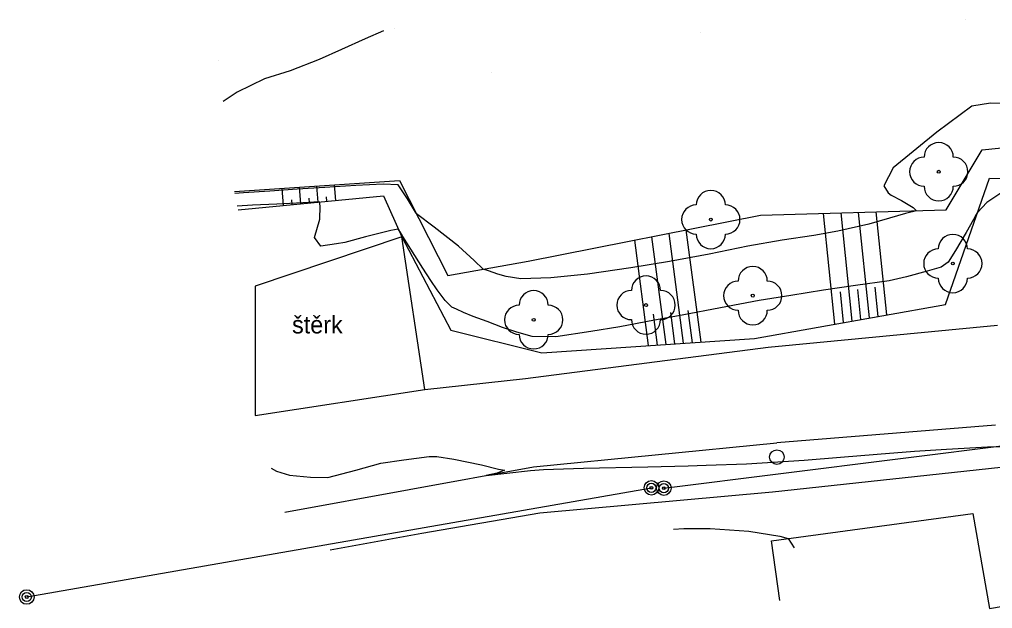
# Model space of a CAD drawing. Extents: x -448957 to -448612, y -1107690 to -1107245.
# Drawn here: x -448905.6 to -448872.22, y -1107404.31 to -1107384.1 of the extents above; entities that cross this region are included whole.
import ezdxf

# ---------------------------------------------------------------- set-up
doc = ezdxf.new("R2010")
doc.units = 0
for name, color, linetype in [('22', 7, 'Continuous'), ('25', 7, 'Continuous'), ('28', 7, 'Continuous'), ('Default', 7, 'Continuous'), ('Vrstva 1', 7, 'Continuous'), ('Vrstva 10', 7, 'Continuous'), ('Vrstva 11', 7, 'Continuous'), ('Vrstva 14', 7, 'Continuous'), ('Vrstva 15', 7, 'Continuous'), ('Vrstva 16', 7, 'Continuous'), ('Vrstva 17', 7, 'Continuous'), ('Vrstva 22', 7, 'Continuous'), ('Vrstva 25', 7, 'Continuous'), ('Vrstva 28', 7, 'Continuous'), ('Vrstva 40', 7, 'Continuous'), ('Vrstva 5', 7, 'Continuous'), ('Vrstva 53', 7, 'Continuous'), ('Vrstva 7', 7, 'Continuous'), ('Vrstva 8', 7, 'Continuous')]:
    doc.layers.add(name, color=color, linetype=linetype)

# ---------------------------------------------------------------- blocks, each defined once
blk = doc.blocks.new('POINT_DISPLAY')
at = {"layer": 'Default'}
blk.add_line((0, 0), (0, 0), dxfattribs=at)
blk = doc.blocks.new('STROM$5')
at = {"layer": '22'}
blk.add_circle((0, 0), 0.5, dxfattribs=at)
for centre, start, end in [((0, 5), 0, 180), ((-5, 0), 90, 270), ((5, 0), 270, 90), ((0, -5), 180, 0)]:
    blk.add_arc(centre, 5, start, end, dxfattribs=at)
blk = doc.blocks.new('SLB$11')
at = {"layer": '25'}
for radius in [2.5, 1.58, 0.5]:
    blk.add_circle((0, 0), radius, dxfattribs=at)
blk = doc.blocks.new('SV$12')
at = {"layer": '28'}
blk.add_circle((0, 0), 2.5, dxfattribs=at)

msp = doc.modelspace()

# ---------------------------------------------------------------- linework, layer by layer
at = {"layer": 'Vrstva 10'}
for p, q in [((-448879.913, -1107395.339), (-448872.051, -1107394.581)), ((-448888.24, -1107396.414), (-448879.913, -1107395.339)), ((-448891.694, -1107396.794), (-448888.24, -1107396.414)), ((-448897.513, -1107397.681), (-448891.694, -1107396.794)), ((-448872.121, -1107398.014), (-448879.623, -1107398.621)), ((-448887.967, -1107399.449), (-448879.623, -1107398.621)), ((-448896.495, -1107401), (-448887.967, -1107399.449))]:
    msp.add_line(p, q, dxfattribs=at)
at = {"layer": 'Vrstva 11'}
for p, q in [((-448892.481, -1107391.555), (-448897.513, -1107393.245)), ((-448891.694, -1107396.794), (-448892.481, -1107391.555)), ((-448897.513, -1107393.245), (-448897.513, -1107397.681))]:
    msp.add_line(p, q, dxfattribs=at)
at = {"layer": 'Vrstva 14'}
for p, q in [((-448872.575, -1107388.576), (-448868.257, -1107388.103)), ((-448873.805, -1107390.629), (-448872.575, -1107388.576)), ((-448898.226, -1107390.005), (-448892.566, -1107389.622)), ((-448892.566, -1107389.622), (-448890.902, -1107392.878)), ((-448873.839, -1107393.875), (-448872.319, -1107389.541)), ((-448872.319, -1107389.541), (-448868.312, -1107389.677)), ((-448898.1, -1107390.624), (-448893.114, -1107390.15)), ((-448893.114, -1107390.15), (-448892.481, -1107391.555)), ((-448880.177, -1107390.815), (-448873.805, -1107390.629)), ((-448888.143, -1107392.393), (-448880.177, -1107390.815)), ((-448892.481, -1107391.555), (-448890.803, -1107394.756)), ((-448890.902, -1107392.878), (-448888.143, -1107392.393)), ((-448880.382, -1107395.044), (-448873.839, -1107393.875)), ((-448890.803, -1107394.756), (-448887.678, -1107395.533)), ((-448887.678, -1107395.533), (-448880.382, -1107395.044))]:
    msp.add_line(p, q, dxfattribs=at)
at = {"layer": 'Vrstva 15'}
for p, q in [((-448896.541, -1107390.476), (-448896.589, -1107389.894)), ((-448895.944, -1107390.419), (-448895.99, -1107389.854)), ((-448895.347, -1107390.362), (-448895.391, -1107389.813)), ((-448894.749, -1107390.305), (-448894.793, -1107389.773)), ((-448896.243, -1107390.447), (-448896.256, -1107390.286)), ((-448895.645, -1107390.391), (-448895.658, -1107390.234)), ((-448895.048, -1107390.334), (-448895.06, -1107390.182)), ((-448877.625, -1107394.551), (-448878.018, -1107390.752)), ((-448877.033, -1107394.446), (-448877.416, -1107390.734)), ((-448876.441, -1107394.34), (-448876.815, -1107390.717)), ((-448875.848, -1107394.234), (-448876.214, -1107390.699)), ((-448883.415, -1107395.247), (-448883.902, -1107391.553)), ((-448882.815, -1107395.207), (-448883.313, -1107391.436)), ((-448882.215, -1107395.167), (-448882.723, -1107391.319)), ((-448884.015, -1107395.287), (-448884.492, -1107391.67)), ((-448876.144, -1107394.287), (-448876.249, -1107393.277)), ((-448877.329, -1107394.499), (-448877.439, -1107393.438)), ((-448876.737, -1107394.393), (-448876.844, -1107393.358)), ((-448883.715, -1107395.267), (-448883.854, -1107394.212)), ((-448883.115, -1107395.227), (-448883.257, -1107394.15)), ((-448882.515, -1107395.187), (-448882.66, -1107394.088))]:
    msp.add_line(p, q, dxfattribs=at)
at = {"layer": 'Vrstva 16'}
for points in [[(-448871.563, -1107386.992), (-448872.295, -1107386.971), (-448872.932, -1107387.071), (-448874.133, -1107387.971), (-448875.629, -1107389.185), (-448875.946, -1107389.812), (-448875.797, -1107390.049), (-448875.7, -1107390.129), (-448875.337, -1107390.304), (-448874.942, -1107390.546), (-448874.83, -1107390.659), (-448875.201, -1107390.761), (-448875.752, -1107390.917), (-448876.466, -1107391.116), (-448877.53, -1107391.362), (-448878.352, -1107391.509), (-448879.434, -1107391.674), (-448880.611, -1107391.88), (-448881.939, -1107392.149), (-448883.304, -1107392.399), (-448884.63, -1107392.625), (-448886.113, -1107392.835), (-448887.37, -1107392.968), (-448888.402, -1107392.994), (-448888.902, -1107392.918), (-448889.184, -1107392.841), (-448889.508, -1107392.726), (-448889.691, -1107392.665), (-448890.002, -1107392.368), (-448890.54, -1107391.871), (-448891.374, -1107391.22), (-448891.981, -1107390.767), (-448891.996, -1107390.745), (-448892.017, -1107390.71), (-448892.291, -1107390.258), (-448892.61, -1107389.767), (-448893.121, -1107389.745), (-448894.053, -1107389.797), (-448895.126, -1107389.858), (-448896.071, -1107389.923), (-448897.007, -1107389.987), (-448897.906, -1107390.044), (-448898.214, -1107390.065)], [(-448883.16, -1107401.579), (-448882.803, -1107401.562), (-448881.91, -1107401.556), (-448880.584, -1107401.652), (-448879.513, -1107401.822), (-448879.233, -1107401.908), (-448879.02, -1107402.227)]]:
    msp.add_lwpolyline(points, dxfattribs=at)
at = {"layer": 'Vrstva 17'}
for points in [[(-448893.113, -1107384.486), (-448893.737, -1107384.768), (-448894.553, -1107385.127), (-448895.317, -1107385.47), (-448896.316, -1107385.866), (-448897.196, -1107386.132), (-448898.129, -1107386.594), (-448898.611, -1107386.918)], [(-448871.727, -1107389.924), (-448872.418, -1107390.376), (-448872.734, -1107390.723), (-448872.779, -1107390.792), (-448872.874, -1107390.959), (-448873.124, -1107391.408), (-448873.489, -1107392.026), (-448873.739, -1107392.422), (-448873.984, -1107392.596), (-448874.459, -1107392.731), (-448875.171, -1107392.931), (-448875.765, -1107393.07), (-448876.925, -1107393.231), (-448878.014, -1107393.385), (-448879.135, -1107393.565), (-448880.225, -1107393.743), (-448881.546, -1107393.995), (-448882.863, -1107394.243), (-448883.813, -1107394.415), (-448885.007, -1107394.644), (-448885.993, -1107394.804), (-448887.195, -1107394.983), (-448888.014, -1107394.979), (-448888.538, -1107394.825), (-448889.024, -1107394.664), (-448889.556, -1107394.457), (-448890.031, -1107394.287), (-448890.361, -1107394.149), (-448890.602, -1107394.034), (-448890.765, -1107393.967), (-448890.993, -1107393.745), (-448891.264, -1107393.376), (-448891.482, -1107393.057), (-448891.756, -1107392.633), (-448892.177, -1107391.98), (-448892.451, -1107391.545), (-448892.543, -1107391.386), (-448892.601, -1107391.289), (-448892.863, -1107391.34), (-448893.73, -1107391.559), (-448894.439, -1107391.75), (-448894.721, -1107391.8), (-448895.26, -1107391.871), (-448895.473, -1107391.584), (-448895.29, -1107390.949), (-448895.28, -1107390.502), (-448895.305, -1107390.358), (-448895.876, -1107390.388), (-448896.766, -1107390.433), (-448897.604, -1107390.474), (-448898.125, -1107390.5)], [(-448896.957, -1107399.495), (-448896.778, -1107399.591), (-448896.333, -1107399.732), (-448895.615, -1107399.805), (-448895.016, -1107399.812), (-448894.06, -1107399.559), (-448893.204, -1107399.315), (-448892.411, -1107399.204), (-448891.539, -1107399.088), (-448891.278, -1107399.09), (-448890.7, -1107399.179), (-448889.75, -1107399.376), (-448889.166, -1107399.521), (-448888.962, -1107399.56), (-448889.214, -1107399.663), (-448889.592, -1107399.745), (-448888.884, -1107399.659), (-448888.064, -1107399.567), (-448887.618, -1107399.54), (-448886.248, -1107399.495), (-448884.045, -1107399.441), (-448882.664, -1107399.409), (-448882.041, -1107399.39), (-448880.659, -1107399.343), (-448878.686, -1107399.222), (-448877.435, -1107399.112), (-448876.173, -1107399.007), (-448874.894, -1107398.907), (-448873.798, -1107398.843), (-448872.395, -1107398.757), (-448871.785, -1107398.743)]]:
    msp.add_lwpolyline(points, dxfattribs=at)
at = {"layer": 'Vrstva 5'}
for p, q in [((-448879.798, -1107401.985), (-448872.9, -1107401.044)), ((-448872.9, -1107401.044), (-448872.322, -1107404.307)), ((-448879.519, -1107404.032), (-448879.798, -1107401.985)), ((-448872.322, -1107404.307), (-448870.425, -1107403.968))]:
    msp.add_line(p, q, dxfattribs=at)
at = {"layer": 'Vrstva 53'}
for p, q in [((-448883.494, -1107400.177), (-448854.847, -1107396.595)), ((-448905.346, -1107403.911), (-448883.921, -1107400.166))]:
    msp.add_line(p, q, dxfattribs=at)
at = {"layer": 'Vrstva 7'}
for p, q in [((-448879.769, -1107400.301), (-448871.513, -1107399.414)), ((-448887.75, -1107401.024), (-448879.769, -1107400.301)), ((-448891.794, -1107401.725), (-448887.75, -1107401.024))]:
    msp.add_line(p, q, dxfattribs=at)
at = {"layer": 'Vrstva 8'}
msp.add_line((-448894.94, -1107402.29), (-448891.794, -1107401.725), dxfattribs=at)

# ---------------------------------------------------------------- block references
at = {"layer": 'Vrstva 1', "xscale": 0.1, "yscale": 0.10000000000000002}
for p in [(-448872.575, -1107388.576), (-448892.566, -1107389.622), (-448872.319, -1107389.541), (-448898.226, -1107390.005), (-448893.114, -1107390.15), (-448893.114, -1107390.15), (-448898.1, -1107390.624), (-448873.805, -1107390.629), (-448880.177, -1107390.815), (-448892.481, -1107391.555), (-448892.481, -1107391.555), (-448892.481, -1107391.555), (-448888.143, -1107392.393), (-448890.902, -1107392.878), (-448897.513, -1107393.245), (-448873.839, -1107393.875), (-448873.839, -1107393.875), (-448890.803, -1107394.756), (-448890.803, -1107394.756), (-448880.382, -1107395.044), (-448887.678, -1107395.533), (-448879.913, -1107395.339), (-448888.24, -1107396.414), (-448891.694, -1107396.794), (-448891.694, -1107396.794), (-448897.513, -1107397.681), (-448879.623, -1107398.621), (-448887.967, -1107399.449), (-448883.921, -1107400.166), (-448879.769, -1107400.301), (-448896.495, -1107401), (-448887.75, -1107401.024), (-448872.9, -1107401.044), (-448891.794, -1107401.725), (-448879.798, -1107401.985), (-448894.94, -1107402.29), (-448905.346, -1107403.911), (-448872.322, -1107404.307)]:
    msp.add_blockref('POINT_DISPLAY', p, dxfattribs=at)
at = {"layer": 'Vrstva 14', "xscale": 0.1, "yscale": 0.10000000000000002}
for p in [(-448873.132, -1107384.099), (-448892.748, -1107384.42), (-448882.239, -1107384.562), (-448898.786, -1107385.518), (-448889.395, -1107385.93)]:
    msp.add_blockref('POINT_DISPLAY', p, dxfattribs=at)
at = {"layer": 'Vrstva 22', "xscale": 0.1, "yscale": 0.10000000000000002}
for p in [(-448874.065, -1107389.322), (-448881.883, -1107390.963), (-448873.581, -1107392.472), (-448880.445, -1107393.574), (-448884.106, -1107393.897), (-448887.959, -1107394.402)]:
    msp.add_blockref('STROM$5', p, dxfattribs=at)
at = {"layer": 'Vrstva 25', "xscale": 0.1, "yscale": 0.10000000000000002}
for p in [(-448883.921, -1107400.166), (-448883.494, -1107400.177), (-448905.346, -1107403.911)]:
    msp.add_blockref('SLB$11', p, dxfattribs=at)
at = {"layer": 'Vrstva 28', "xscale": 0.1, "yscale": 0.10000000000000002}
msp.add_blockref('SV$12', (-448879.618, -1107399.112), dxfattribs=at)

# ---------------------------------------------------------------- texts
at = {"layer": 'Vrstva 40'}
msp.add_text('štěrk', height=0.6, dxfattribs=at).set_placement((-448896.247, -1107394.87))

doc.saveas('drawing.dxf')
